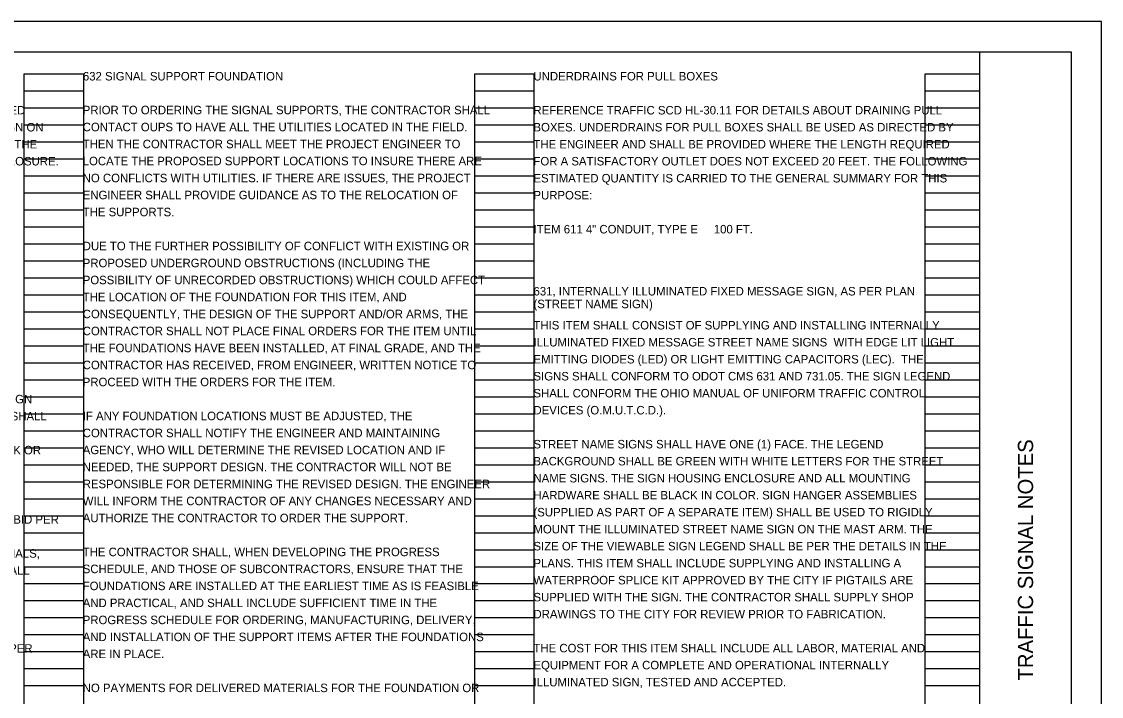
# Model space of a CAD drawing. Extents: x 0 to 34, y 0 to 22.
# Drawn here: x 16.22 to 34, y 10.88 to 22 of the extents above; entities that cross this region are included whole.
import ezdxf

# ---------------------------------------------------------------- set-up
doc = ezdxf.new("R2010")
doc.units = 0
for name, color, linetype in [('SH_Border', 7, 'Continuous'), ('SH_Cut_Line', 7, 'Continuous'), ('SH_Data', 7, 'Continuous'), ('SH_Text', 7, 'Continuous')]:
    doc.layers.add(name, color=color, linetype=linetype)

msp = doc.modelspace()

# ---------------------------------------------------------------- linework, layer by layer
at = {"layer": 'SH_Border'}
msp.add_line((32, 0.5), (32, 21.5), dxfattribs=at)
msp.add_lwpolyline([(1.5, 21.5), (33.5, 21.5), (33.5, 0.5), (1.5, 0.5)], close=True, dxfattribs=at)
at = {"layer": 'SH_Cut_Line'}
msp.add_lwpolyline([(0, 0), (34, 0), (34, 22), (0, 22)], close=True, dxfattribs=at)
at = {"layer": 'SH_Data'}
for p, q in [((16.26, 0.98), (16.26, 21.14)), ((16.26, 21.14), (17.24, 21.14)), ((17.24, 0.98), (17.24, 21.14)), ((23.68, 0.98), (23.68, 21.14)), ((23.68, 21.14), (24.66, 21.14)), ((24.66, 0.98), (24.66, 21.14)), ((31.1, 0.98), (31.1, 21.14)), ((31.1, 21.14), (32, 21.14)), ((32, 0.98), (32, 21.14)), ((16.26, 20.86), (17.24, 20.86)), ((23.68, 20.86), (24.66, 20.86)), ((31.1, 20.86), (32, 20.86)), ((16.26, 20.58), (17.24, 20.58)), ((23.68, 20.58), (24.66, 20.58)), ((31.1, 20.58), (32, 20.58)), ((16.26, 20.3), (17.24, 20.3)), ((23.68, 20.3), (24.66, 20.3)), ((31.1, 20.3), (32, 20.3)), ((16.26, 20.02), (17.24, 20.02)), ((23.68, 20.02), (24.66, 20.02)), ((31.1, 20.02), (32, 20.02)), ((16.26, 19.74), (17.24, 19.74)), ((23.68, 19.74), (24.66, 19.74)), ((31.1, 19.74), (32, 19.74)), ((16.26, 19.46), (17.24, 19.46)), ((23.68, 19.46), (24.66, 19.46)), ((31.1, 19.46), (32, 19.46)), ((16.26, 19.18), (17.24, 19.18)), ((23.68, 19.18), (24.66, 19.18)), ((31.1, 19.18), (32, 19.18)), ((16.26, 18.9), (17.24, 18.9)), ((23.68, 18.9), (24.66, 18.9)), ((31.1, 18.9), (32, 18.9)), ((16.26, 18.62), (17.24, 18.62)), ((23.68, 18.62), (24.66, 18.62)), ((31.1, 18.62), (32, 18.62)), ((16.26, 18.34), (17.24, 18.34)), ((23.68, 18.34), (24.66, 18.34)), ((31.1, 18.34), (32, 18.34)), ((16.26, 18.06), (17.24, 18.06)), ((23.68, 18.06), (24.66, 18.06)), ((31.1, 18.06), (32, 18.06)), ((16.26, 17.78), (17.24, 17.78)), ((23.68, 17.78), (24.66, 17.78)), ((31.1, 17.78), (32, 17.78)), ((16.26, 17.5), (17.24, 17.5)), ((23.68, 17.5), (24.66, 17.5)), ((31.1, 17.5), (32, 17.5)), ((16.26, 17.22), (17.24, 17.22)), ((23.68, 17.22), (24.66, 17.22)), ((31.1, 17.22), (32, 17.22)), ((16.26, 16.94), (17.24, 16.94)), ((23.68, 16.94), (24.66, 16.94)), ((31.1, 16.94), (32, 16.94)), ((16.26, 16.66), (17.24, 16.66)), ((23.68, 16.66), (24.66, 16.66)), ((31.1, 16.66), (32, 16.66)), ((16.26, 16.38), (17.24, 16.38)), ((23.68, 16.38), (24.66, 16.38)), ((31.1, 16.38), (32, 16.38)), ((16.26, 16.1), (17.24, 16.1)), ((23.68, 16.1), (24.66, 16.1)), ((31.1, 16.1), (32, 16.1)), ((16.26, 15.82), (17.24, 15.82)), ((23.68, 15.82), (24.66, 15.82)), ((31.1, 15.82), (32, 15.82)), ((16.26, 15.54), (17.24, 15.54)), ((23.68, 15.54), (24.66, 15.54)), ((31.1, 15.54), (32, 15.54)), ((16.26, 15.26), (17.24, 15.26)), ((23.68, 15.26), (24.66, 15.26)), ((31.1, 15.26), (32, 15.26)), ((16.26, 14.98), (17.24, 14.98)), ((23.68, 14.98), (24.66, 14.98)), ((31.1, 14.98), (32, 14.98)), ((16.26, 14.7), (17.24, 14.7)), ((23.68, 14.7), (24.66, 14.7)), ((31.1, 14.7), (32, 14.7)), ((16.26, 14.42), (17.24, 14.42)), ((23.68, 14.42), (24.66, 14.42)), ((31.1, 14.42), (32, 14.42)), ((16.26, 14.14), (17.24, 14.14)), ((23.68, 14.14), (24.66, 14.14)), ((31.1, 14.14), (32, 14.14)), ((16.26, 13.86), (17.24, 13.86)), ((23.68, 13.86), (24.66, 13.86)), ((31.1, 13.86), (32, 13.86)), ((16.26, 13.58), (17.24, 13.58)), ((23.68, 13.58), (24.66, 13.58)), ((31.1, 13.58), (32, 13.58)), ((16.26, 13.3), (17.24, 13.3)), ((23.68, 13.3), (24.66, 13.3)), ((31.1, 13.3), (32, 13.3)), ((16.26, 13.02), (17.24, 13.02)), ((23.68, 13.02), (24.66, 13.02)), ((31.1, 13.02), (32, 13.02)), ((16.26, 12.74), (17.24, 12.74)), ((23.68, 12.74), (24.66, 12.74)), ((31.1, 12.74), (32, 12.74)), ((16.26, 12.46), (17.24, 12.46)), ((23.68, 12.46), (24.66, 12.46)), ((31.1, 12.46), (32, 12.46)), ((16.26, 12.18), (17.24, 12.18)), ((23.68, 12.18), (24.66, 12.18)), ((31.1, 12.18), (32, 12.18)), ((16.26, 11.9), (17.24, 11.9)), ((23.68, 11.9), (24.66, 11.9)), ((31.1, 11.9), (32, 11.9)), ((16.26, 11.62), (17.24, 11.62)), ((23.68, 11.62), (24.66, 11.62)), ((31.1, 11.62), (32, 11.62)), ((16.26, 11.34), (17.24, 11.34)), ((23.68, 11.34), (24.66, 11.34)), ((31.1, 11.34), (32, 11.34)), ((16.26, 11.06), (17.24, 11.06)), ((23.68, 11.06), (24.66, 11.06)), ((31.1, 11.06), (32, 11.06))]:
    msp.add_line(p, q, dxfattribs=at)

# ---------------------------------------------------------------- texts
msp.add_text('TRAFFIC SIGNAL NOTES', height=0.25, rotation=90, dxfattribs=at).set_placement((32.875, 11.144))
at = {"layer": 'SH_Text'}
for s, p in [('632 SIGNAL SUPPORT FOUNDATION', (17.227, 21.03)), ('UNDERDRAINS FOR PULL BOXES', (24.647, 21.03)), ('THE CONTRACTOR SHALL PROVIDE AND INSTALL A SOLID FILLED RED ', (9.807, 20.47)), ('PRIOR TO ORDERING THE SIGNAL SUPPORTS, THE CONTRACTOR SHALL ', (17.224, 20.473)), ('REFERENCE TRAFFIC SCD HL-30.11 FOR DETAILS ABOUT DRAINING PULL ', (24.647, 20.47)), ('SYMBOL, SOLID FILLED WHITE ARROW NO RIGHT TURN SYMBOL SIGN ON ', (9.807, 20.19)), ('CONTACT OUPS TO HAVE ALL THE UTILITIES LOCATED IN THE FIELD. ', (17.224, 20.193)), ('BOXES. UNDERDRAINS FOR PULL BOXES SHALL BE USED AS DIRECTED BY ', (24.647, 20.19)), ('THE TRAFFIC SIGNAL MAST ARM AT THE LOCATIONS INDICATED ON THE ', (9.807, 19.91)), ('THEN THE CONTRACTOR SHALL MEET THE PROJECT ENGINEER TO ', (17.224, 19.913)), ('THE ENGINEER AND SHALL BE PROVIDED WHERE THE LENGTH REQUIRED ', (24.647, 19.91)), ('PLANS. THE SYMBOL SIGN SHALL BE A WEATHER TIGHT NEMA ENCLOSURE. ', (9.807, 19.63)), ('LOCATE THE PROPOSED SUPPORT LOCATIONS TO INSURE THERE ARE ', (17.224, 19.633)), ('FOR A SATISFACTORY OUTLET DOES NOT EXCEED 20 FEET. THE FOLLOWING ', (24.647, 19.63)), ('NO CONFLICTS WITH UTILITIES. IF THERE ARE ISSUES, THE PROJECT ', (17.224, 19.353)), ('ESTIMATED QUANTITY IS CARRIED TO THE GENERAL SUMMARY FOR THIS ', (24.647, 19.35)), ('ENGINEER SHALL PROVIDE GUIDANCE AS TO THE RELOCATION OF ', (17.224, 19.073)), ('PURPOSE:', (24.647, 19.07)), ('THE SUPPORTS.', (17.224, 18.793)), ('ITEM 611 4" CONDUIT, TYPE E     100 FT.', (24.647, 18.51)), ('DUE TO THE FURTHER POSSIBILITY OF CONFLICT WITH EXISTING OR ', (17.224, 18.233)), ('PROPOSED UNDERGROUND OBSTRUCTIONS (INCLUDING THE ', (17.224, 17.953)), ('POSSIBILITY OF UNRECORDED OBSTRUCTIONS) WHICH COULD AFFECT ', (17.224, 17.673)), ('631, INTERNALLY ILLUMINATED FIXED MESSAGE SIGN, AS PER PLAN', (24.647, 17.488)), ('THE LOCATION OF THE FOUNDATION FOR THIS ITEM, AND ', (17.224, 17.393)), ('CONSEQUENTLY, THE DESIGN OF THE SUPPORT AND/OR ARMS, THE ', (17.224, 17.113)), ('(STREET NAME SIGN)', (24.647, 17.278)), ('CONTRACTOR SHALL NOT PLACE FINAL ORDERS FOR THE ITEM UNTIL ', (17.224, 16.833)), ('THIS ITEM SHALL CONSIST OF SUPPLYING AND INSTALLING INTERNALLY ', (24.647, 16.928)), ('ILLUMINATED FIXED MESSAGE STREET NAME SIGNS  WITH EDGE LIT LIGHT ', (24.647, 16.648)), ('THE FOUNDATIONS HAVE BEEN INSTALLED, AT FINAL GRADE, AND THE ', (17.224, 16.553)), ('CONTRACTOR HAS RECEIVED, FROM ENGINEER, WRITTEN NOTICE TO ', (17.224, 16.273)), ('EMITTING DIODES (LED) OR LIGHT EMITTING CAPACITORS (LEC).  THE ', (24.647, 16.368)), ('SIGNS SHALL CONFORM TO ODOT CMS 631 AND 731.05. THE SIGN LEGEND ', (24.647, 16.088)), ('PROCEED WITH THE ORDERS FOR THE ITEM.', (17.224, 15.993)), ('THE MAST ARM MOUNTING BRACKET SHALL BE SUPPLIED BY THE SIGN ', (9.807, 15.71)), ('SHALL CONFORM THE OHIO MANUAL OF UNIFORM TRAFFIC CONTROL ', (24.647, 15.808)), ('DEVICES (O.M.U.T.C.D.).', (24.647, 15.528)), ('MANUFACTURER AND INSTALLED BY THE CONTRACTOR. THE SIGN SHALL ', (9.807, 15.43)), ('IF ANY FOUNDATION LOCATIONS MUST BE ADJUSTED, THE ', (17.224, 15.433)), ('CONTRACTOR SHALL NOTIFY THE ENGINEER AND MAINTAINING ', (17.224, 15.153)), ('PREEMPTION CALL. THE REMAINING TIME THE SIGN SHALL BE BLANK OR ', (9.807, 14.87)), ('AGENCY, WHO WILL DETERMINE THE REVISED LOCATION AND IF', (17.224, 14.873)), ('STREET NAME SIGNS SHALL HAVE ONE (1) FACE. THE LEGEND ', (24.647, 14.968)), ('BACKGROUND SHALL BE GREEN WITH WHITE LETTERS FOR THE STREET ', (24.647, 14.688)), ('NEEDED, THE SUPPORT DESIGN. THE CONTRACTOR WILL NOT BE ', (17.224, 14.593)), ('RESPONSIBLE FOR DETERMINING THE REVISED DESIGN. THE ENGINEER ', (17.224, 14.313)), ('NAME SIGNS. THE SIGN HOUSING ENCLOSURE AND ALL MOUNTING ', (24.647, 14.408)), ('HARDWARE SHALL BE BLACK IN COLOR. SIGN HANGER ASSEMBLIES ', (24.647, 14.128)), ('WILL INFORM THE CONTRACTOR OF ANY CHANGES NECESSARY AND ', (17.224, 14.033)), ('AUTHORIZE THE CONTRACTOR TO ORDER THE SUPPORT.', (17.224, 13.753)), ('(SUPPLIED AS PART OF A SEPARATE ITEM) SHALL BE USED TO RIGIDLY ', (24.647, 13.848)), ('PAYMENT FOR THE ABOVE ITEM SHALL BE PAID AT THE UNIT PRICE BID PER ', (9.788, 13.728)), ('MOUNT THE ILLUMINATED STREET NAME SIGN ON THE MAST ARM. THE ', (24.647, 13.568)), ('SIZE OF THE VIEWABLE SIGN LEGEND SHALL BE PER THE DETAILS IN THE ', (24.647, 13.288)), ('COMPLETE. PRICE SHALL INCLUDE ALL LABOR, EQUIPMENT, MATERIALS, ', (9.788, 13.168)), ('THE CONTRACTOR SHALL, WHEN DEVELOPING THE PROGRESS ', (17.224, 13.193)), ('MOUNTING HARDWARE FOR RIGID MOUNTING, POWER CABLE AND ALL ', (9.788, 12.888)), ('SCHEDULE, AND THOSE OF SUBCONTRACTORS, ENSURE THAT THE ', (17.224, 12.913)), ('PLANS. THIS ITEM SHALL INCLUDE SUPPLYING AND INSTALLING A ', (24.647, 13.008)), ('WATERPROOF SPLICE KIT APPROVED BY THE CITY IF PIGTAILS ARE ', (24.647, 12.728)), ('FOUNDATIONS ARE INSTALLED AT THE EARLIEST TIME AS IS FEASIBLE ', (17.224, 12.633)), ('AND PRACTICAL, AND SHALL INCLUDE SUFFICIENT TIME IN THE ', (17.224, 12.353)), ('SUPPLIED WITH THE SIGN. THE CONTRACTOR SHALL SUPPLY SHOP ', (24.647, 12.448)), ('DRAWINGS TO THE CITY FOR REVIEW PRIOR TO FABRICATION.', (24.647, 12.168)), ('PROGRESS SCHEDULE FOR ORDERING, MANUFACTURING, DELIVERY, ', (17.224, 12.073)), ('AND INSTALLATION OF THE SUPPORT ITEMS AFTER THE FOUNDATIONS ', (17.224, 11.793)), ('632 PEDESTRIAN SIGNAL HEAD (LED), (COUNTDOWN), TYPE D2, AS PER ', (9.824, 11.603)), ('THE COST FOR THIS ITEM SHALL INCLUDE ALL LABOR, MATERIAL AND ', (24.647, 11.608)), ('ARE IN PLACE.', (17.224, 11.513)), ('EQUIPMENT FOR A COMPLETE AND OPERATIONAL INTERNALLY ', (24.647, 11.328)), ('NO PAYMENTS FOR DELIVERED MATERIALS FOR THE FOUNDATION OR ', (17.224, 10.953)), ('ILLUMINATED SIGN, TESTED AND ACCEPTED.', (24.647, 11.048))]:
    msp.add_text(s, height=0.14, dxfattribs=at).set_placement(p)

doc.saveas('drawing.dxf')
